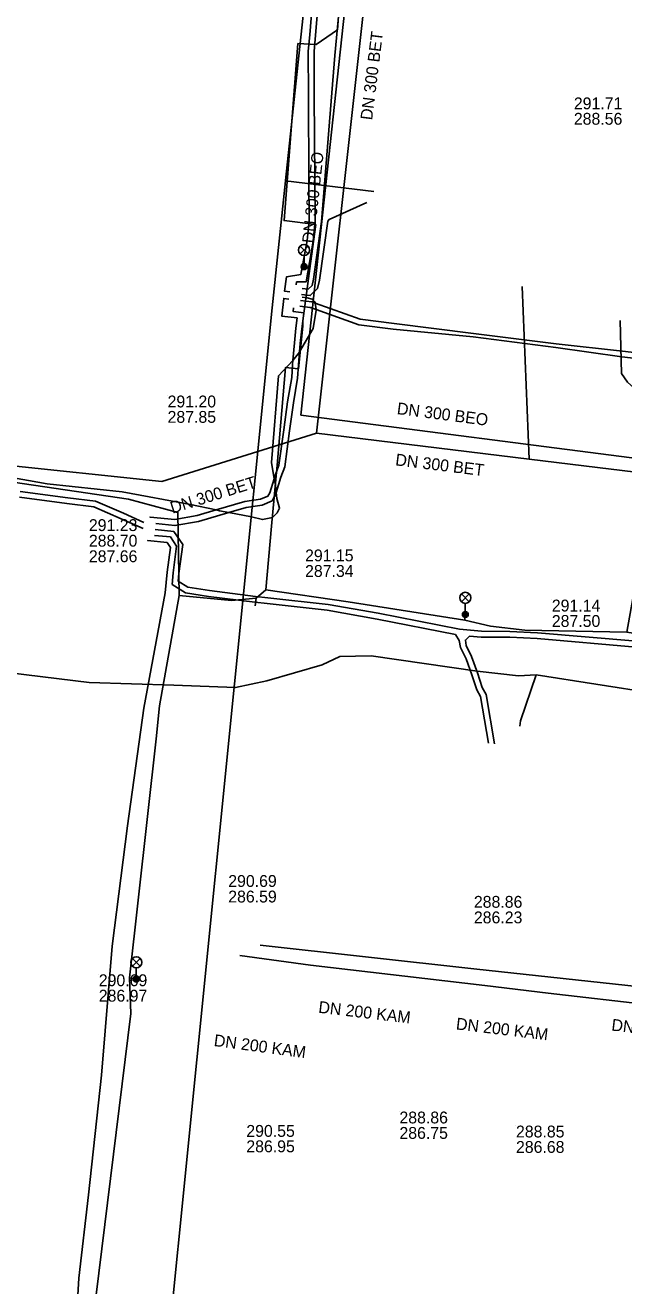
# Model space of a CAD drawing. Extents: x -595540 to -593988, y -1160850 to -1159202.
# Drawn here: x -594420.8 to -594380.4, y -1160378.8 to -1160293.7 of the extents above; entities that cross this region are included whole.
import ezdxf

# ---------------------------------------------------------------- set-up
doc = ezdxf.new("R2010")
doc.units = 0
for name, color, linetype in [('BVK-DESTOVA_popisy', 7, 'Continuous'), ('BVK-DESTOVA_trasa sítě', 7, 'Continuous'), ('BVK-SPLASKOVA_popisy', 7, 'Continuous'), ('BVK-SPLASKOVA_trasa sítě', 7, 'Continuous'), ('BVK-VODOVOD_trasa sítě', 7, 'Continuous'), ('CETIN_kabel podzemní', 7, 'Continuous'), ('DESTOVA-NEPROVOZOVANA_popisy', 7, 'Continuous'), ('DESTOVA_trasa neprovozované sítě', 7, 'Continuous'), ('EON-NN_kabel', 7, 'Continuous'), ('EON-VN_kabel', 7, 'Continuous'), ('SPLASKOVA_neprovozovaná  trasa sítě', 7, 'Continuous'), ('SPLASKOVA_popisy neprovozované sítě', 7, 'Continuous'), ('TSB_kabel VO', 7, 'Continuous'), ('TSB_lampy VO', 7, 'Continuous')]:
    doc.layers.add(name, color=color, linetype=linetype)

msp = doc.modelspace()

# ---------------------------------------------------------------- linework, layer by layer
at = {"layer": 'BVK-DESTOVA_popisy'}
msp.add_line((-594401.885, -1160330.032), (-594401.885, -1160330.032), dxfattribs=at)
at = {"layer": 'BVK-DESTOVA_trasa sítě'}
for points in [[(-594395.668, -1160272.407), (-594397.915, -1160292.572), (-594397.935, -1160292.748), (-594401.113, -1160321.262)], [(-594401.113, -1160321.262), (-594386.76, -1160323.019), (-594375.871, -1160324.352)]]:
    msp.add_lwpolyline(points, dxfattribs=at)
at = {"layer": 'BVK-SPLASKOVA_popisy'}
for p, q in [((-594383.751, -1160298.621), (-594383.751, -1160298.621)), ((-594411.161, -1160318.726), (-594411.161, -1160318.726)), ((-594385.238, -1160332.49), (-594385.238, -1160332.49))]:
    msp.add_line(p, q, dxfattribs=at)
at = {"layer": 'BVK-SPLASKOVA_trasa sítě'}
for p, q in [((-594396.883, -1160271.348), (-594402.178, -1160320.04)), ((-594402.178, -1160320.04), (-594376.811, -1160323.33))]:
    msp.add_line(p, q, dxfattribs=at)
at = {"layer": 'BVK-VODOVOD_trasa sítě'}
msp.add_line((-594403.199, -1160304.249), (-594397.24, -1160304.965), dxfattribs=at)
msp.add_lwpolyline([(-594414.304, -1160415.018), (-594414.26, -1160414.24), (-594404.1, -1160312.8), (-594403.199, -1160304.249), (-594403.197, -1160304.228), (-594393.45, -1160213.01), (-594381.18, -1160113.49), (-594372.864, -1160046.537), (-594372.845, -1160046.405)], dxfattribs=at)
at = {"layer": 'CETIN_kabel podzemní'}
for points in [[(-594484.42, -1160349.04), (-594484.05, -1160346.76), (-594483.66, -1160343.45), (-594482.72, -1160335.55), (-594481.74, -1160328.1), (-594481.2, -1160327.76), (-594478.86, -1160327.53), (-594466.54, -1160325.52), (-594458, -1160326.73), (-594452.76, -1160330.16), (-594444.1, -1160335.49), (-594430.62, -1160336.35), (-594416.44, -1160338.08), (-594410.73, -1160338.25), (-594406.57, -1160338.42), (-594404.47, -1160337.96), (-594400.72, -1160336.89), (-594399.54, -1160336.32), (-594397.42, -1160336.27), (-594390.27, -1160337.31), (-594387.49, -1160337.63), (-594386.29, -1160337.57)], [(-594386.29, -1160337.57), (-594387.36, -1160340.67), (-594387.4, -1160341.02)], [(-594386.29, -1160337.57), (-594378.24, -1160338.82), (-594374.04, -1160339.1), (-594368.53, -1160339.75), (-594365.35, -1160340.12), (-594364.77, -1160340.19)]]:
    msp.add_lwpolyline(points, dxfattribs=at)
at = {"layer": 'DESTOVA-NEPROVOZOVANA_popisy'}
for p, q in [((-594416.47, -1160329.965), (-594416.47, -1160329.965)), ((-594407.068, -1160352.915), (-594407.068, -1160352.915)), ((-594390.496, -1160354.321), (-594390.496, -1160354.321))]:
    msp.add_line(p, q, dxfattribs=at)
at = {"layer": 'DESTOVA_trasa neprovozované sítě'}
for p, q in [((-594387.235, -1160311.378), (-594386.76, -1160323.019)), ((-594454.646, -1160320.033), (-594411.539, -1160324.521)), ((-594411.539, -1160324.521), (-594401.113, -1160321.262)), ((-594404.921, -1160355.792), (-594390.492, -1160357.393)), ((-594390.492, -1160357.393), (-594368.695, -1160359.751))]:
    msp.add_line(p, q, dxfattribs=at)
at = {"layer": 'EON-NN_kabel'}
for points in [[(-594394.305, -1160238.002), (-594394.305, -1160238.183), (-594394.168, -1160238.409), (-594393.838, -1160238.499), (-594393.681, -1160238.791), (-594394.009, -1160241.492), (-594394.9, -1160250.248), (-594395.827, -1160258.292), (-594397.026, -1160267.983), (-594397.728, -1160272.871), (-594398.016, -1160276.318), (-594398.324, -1160281.565), (-594399.215, -1160288.846), (-594399.869, -1160295.788), (-594400.773, -1160306.992), (-594401.305, -1160310.873), (-594401.401, -1160311.295), (-594401.68, -1160311.561), (-594402.087, -1160311.513)], [(-594401.216, -1160290.139), (-594401.568, -1160294.397), (-594401.67, -1160295.504), (-594401.661, -1160298.46), (-594401.634, -1160304.184), (-594401.597, -1160306.916), (-594401.744, -1160308.27), (-594402.166, -1160310.552), (-594403.148, -1160310.72), (-594403.263, -1160311.69), (-594402.919, -1160311.73)], [(-594400.818, -1160290.173), (-594401.17, -1160294.431), (-594401.27, -1160295.522), (-594401.261, -1160298.458), (-594401.234, -1160304.18), (-594401.197, -1160306.934), (-594401.346, -1160308.312), (-594401.803, -1160311.046), (-594402.46, -1160311.068), (-594402.482, -1160311.261)], [(-594402.135, -1160311.91), (-594401.54, -1160311.981), (-594401.038, -1160311.501), (-594400.911, -1160310.945), (-594400.352, -1160306.966), (-594400.268, -1160306.851), (-594397.722, -1160305.704)], [(-594402.23, -1160312.705), (-594401.531, -1160312.788), (-594401.144, -1160312.928), (-594398.262, -1160313.966), (-594395.93, -1160314.254), (-594390.544, -1160314.774), (-594384.971, -1160315.481), (-594380.518, -1160316.122), (-594376.399, -1160316.597), (-594372.566, -1160316.533), (-594371.747, -1160316.261), (-594371.18, -1160315.757), (-594370.718, -1160314.861), (-594370.774, -1160313.871), (-594370.857, -1160312.452), (-594370.97, -1160312.168), (-594377.717, -1160311.167)], [(-594402.182, -1160312.308), (-594401.438, -1160312.397), (-594401.193, -1160312.485), (-594398.168, -1160313.574), (-594395.88, -1160313.858), (-594390.514, -1160314.537), (-594384.945, -1160315.242), (-594380.474, -1160315.724), (-594376.379, -1160316.197), (-594372.634, -1160316.135), (-594371.951, -1160315.907), (-594371.502, -1160315.507), (-594371.124, -1160314.775), (-594371.174, -1160313.893), (-594371.254, -1160312.53), (-594377.776, -1160311.562)], [(-594402.09, -1160312.08), (-594401.74, -1160312.14), (-594401.4, -1160312.22), (-594401.2, -1160312.42), (-594401.193, -1160312.485), (-594401.144, -1160312.928), (-594401.14, -1160312.96), (-594401.34, -1160314.21), (-594402.257, -1160315.785), (-594402.26, -1160315.79), (-594402.707, -1160316.356), (-594402.71, -1160316.36), (-594403.67, -1160317.39), (-594404.15, -1160323.25), (-594403.965, -1160324.339), (-594403.89, -1160324.78), (-594403.841, -1160325.258), (-594403.8, -1160325.66), (-594403.6, -1160326.33), (-594403.77, -1160326.64), (-594404.08, -1160326.96), (-594404.76, -1160327.09), (-594405.5, -1160326.9), (-594407.024, -1160326.609), (-594407.65, -1160326.49), (-594407.877, -1160326.443), (-594409.62, -1160326.08), (-594414.23, -1160325.22), (-594419.28, -1160324.67), (-594422.18, -1160324.16)], [(-594412.341, -1160326.942), (-594412.339, -1160326.918), (-594410.679, -1160327.089), (-594409.167, -1160326.821), (-594407.877, -1160326.443), (-594405.938, -1160325.874), (-594404.884, -1160325.724), (-594404.393, -1160325.519), (-594404.273, -1160325.294), (-594403.965, -1160324.339), (-594403.892, -1160324.112), (-594403.648, -1160323.43), (-594403.32, -1160321.047), (-594403.07, -1160319.159), (-594402.785, -1160317.504), (-594402.731, -1160316.635), (-594402.707, -1160316.356), (-594402.606, -1160315.179), (-594402.507, -1160314.182), (-594402.424, -1160313.49), (-594403.462, -1160313.368), (-594403.321, -1160312.18), (-594402.977, -1160312.221)], [(-594402.668, -1160312.8), (-594402.698, -1160313.054), (-594401.979, -1160313.139), (-594402.109, -1160314.226), (-594402.208, -1160315.215), (-594402.257, -1160315.785), (-594402.333, -1160316.665), (-594402.387, -1160317.55), (-594402.674, -1160319.219), (-594402.924, -1160321.101), (-594403.258, -1160323.526), (-594403.514, -1160324.24), (-594403.841, -1160325.258), (-594403.903, -1160325.45), (-594404.107, -1160325.833), (-594404.778, -1160326.112), (-594405.854, -1160326.266), (-594407.024, -1160326.609), (-594409.075, -1160327.211), (-594410.668, -1160327.493), (-594411.959, -1160327.359)], [(-594412.755, -1160327.279), (-594414.142, -1160326.667), (-594416.019, -1160325.852), (-594417.9, -1160325.615), (-594421.105, -1160325.186)], [(-594412.798, -1160327.697), (-594414.302, -1160327.033), (-594416.125, -1160326.242), (-594417.952, -1160326.011), (-594421.157, -1160325.582)], [(-594379.503, -1160335.294), (-594386.196, -1160334.721), (-594388.065, -1160334.632), (-594389.978, -1160334.614), (-594391.462, -1160334.49), (-594396.956, -1160333.402), (-594400.331, -1160332.81), (-594404.392, -1160332.363), (-594405.233, -1160332.273), (-594408.343, -1160331.88), (-594409.803, -1160331.655), (-594410.442, -1160331.254), (-594410.393, -1160330.721), (-594410.142, -1160328.777), (-594410.742, -1160327.887), (-594412.001, -1160327.757)], [(-594412.502, -1160328.484), (-594412.504, -1160328.509), (-594411.197, -1160328.643), (-594410.974, -1160328.974), (-594411.188, -1160330.633), (-594411.316, -1160332.026), (-594412.763, -1160339.798), (-594413.864, -1160347.737), (-594414.896, -1160355.861), (-594415.623, -1160364.549), (-594416.501, -1160372.621), (-594417.155, -1160378.242), (-594417.531, -1160384.696), (-594418.347, -1160395.909), (-594419.494, -1160401.414), (-594419.575, -1160402.57), (-594419.868, -1160403.022), (-594419.994, -1160403.039), (-594420.297, -1160402.993)], [(-594389.511, -1160342.169), (-594390.055, -1160339.027), (-594390.299, -1160338.575), (-594390.625, -1160337.558), (-594391.014, -1160336.48), (-594391.397, -1160335.714), (-594391.489, -1160335.241), (-594391.745, -1160334.841), (-594397.03, -1160333.796), (-594400.387, -1160333.206), (-594404.436, -1160332.761), (-594405.279, -1160332.671), (-594408.399, -1160332.276), (-594409.945, -1160332.037), (-594410.862, -1160331.465), (-594410.79, -1160330.677), (-594410.558, -1160328.875), (-594410.969, -1160328.265), (-594412.042, -1160328.154)], [(-594379.545, -1160335.692), (-594386.222, -1160335.121), (-594388.077, -1160335.032), (-594389.996, -1160335.014), (-594390.783, -1160334.948), (-594391.072, -1160335.223), (-594391.015, -1160335.584), (-594390.646, -1160336.322), (-594390.247, -1160337.428), (-594389.929, -1160338.417), (-594389.671, -1160338.895), (-594389.098, -1160342.214)]]:
    msp.add_lwpolyline(points, dxfattribs=at)
at = {"layer": 'EON-VN_kabel'}
msp.add_lwpolyline([(-594380.637, -1160313.672), (-594380.543, -1160317.23), (-594380.125, -1160317.817), (-594379.707, -1160318.215), (-594377.689, -1160318.817), (-594372.185, -1160319.28), (-594369.39, -1160319.548), (-594364.66, -1160320.217), (-594362.154, -1160320.531), (-594357.005, -1160321.141), (-594354.472, -1160321.439), (-594346.476, -1160322.315), (-594344.196, -1160322.524), (-594336.591, -1160323.343), (-594326.615, -1160324.399)], dxfattribs=at)
at = {"layer": 'SPLASKOVA_neprovozovaná  trasa sítě'}
for p, q in [((-594406.281, -1160356.497), (-594401.518, -1160357.132)), ((-594401.518, -1160357.132), (-594389.747, -1160358.51)), ((-594389.747, -1160358.51), (-594385.476, -1160359.023)), ((-594385.476, -1160359.023), (-594368.316, -1160361.006))]:
    msp.add_line(p, q, dxfattribs=at)
at = {"layer": 'SPLASKOVA_popisy neprovozované sítě'}
for p, q in [((-594415.801, -1160357.759), (-594415.801, -1160357.759)), ((-594395.518, -1160367.016), (-594395.518, -1160367.016)), ((-594405.848, -1160367.92), (-594405.848, -1160367.92)), ((-594387.655, -1160367.962), (-594387.655, -1160367.962))]:
    msp.add_line(p, q, dxfattribs=at)
at = {"layer": 'TSB_kabel VO'}
for points in [[(-594399.037, -1160285.107), (-594399.704, -1160294.063), (-594401.144, -1160295.049), (-594402.367, -1160294.99), (-594403.306, -1160306.925), (-594401.169, -1160307.193), (-594401.554, -1160310.162), (-594401.951, -1160310.035), (-594401.554, -1160310.162), (-594402.043, -1160313.676), (-594402.035, -1160314.044), (-594402.33, -1160316.925), (-594403.199, -1160316.833), (-594403.763, -1160323.43), (-594404.148, -1160327.534), (-594404.54, -1160331.835), (-594405.18, -1160332.399), (-594405.258, -1160332.9)], [(-594364.854, -1160292.94), (-594365.189, -1160296.792), (-594365.822, -1160300.266), (-594366.415, -1160306.186), (-594366.233, -1160308.823), (-594366.643, -1160308.879), (-594366.233, -1160308.823), (-594366.783, -1160311.834), (-594367.266, -1160314.261), (-594367.93, -1160317.548), (-594371.575, -1160318.731), (-594374.987, -1160319.911), (-594377.854, -1160319.656), (-594378.681, -1160326.238), (-594380.182, -1160334.69), (-594387.061, -1160334.538), (-594389.368, -1160334.272), (-594391.113, -1160333.864), (-594398.984, -1160332.628), (-594404.54, -1160331.835), (-594405.18, -1160332.399), (-594405.258, -1160332.9)], [(-594505.239, -1160320.305), (-594504.78, -1160320.38), (-594503.646, -1160321.344), (-594496.566, -1160321.991), (-594496.491, -1160323.072), (-594495.676, -1160323.1), (-594489.541, -1160324.25), (-594486.738, -1160324.515), (-594485.761, -1160321.864), (-594482.876, -1160319.267), (-594477.618, -1160318.31), (-594476.538, -1160319.246), (-594475.733, -1160318.696), (-594448.99, -1160321.769), (-594423.733, -1160324.263), (-594413.793, -1160325.724), (-594410.466, -1160326.608), (-594410.38, -1160332.22), (-594406.852, -1160332.549), (-594405.18, -1160332.399), (-594405.258, -1160332.9)], [(-594405.258, -1160332.9), (-594405.18, -1160332.399), (-594406.852, -1160332.549), (-594410.38, -1160332.22), (-594411.697, -1160339.647), (-594411.924, -1160341.872), (-594413.732, -1160357.988), (-594413.273, -1160358.076), (-594413.732, -1160357.988), (-594413.63, -1160360.4), (-594416.373, -1160382.649), (-594416.561, -1160384.891), (-594416.845, -1160386.589), (-594416.45, -1160386.594), (-594416.845, -1160386.589), (-594417.162, -1160395.776), (-594417.746, -1160401.774), (-594418.188, -1160404.708), (-594418.599, -1160404.664)], [(-594327.555, -1160341.113), (-594343.576, -1160339.066), (-594346.07, -1160338.981), (-594348.326, -1160338.745), (-594348.266, -1160338.367), (-594348.326, -1160338.745), (-594365.579, -1160336.664), (-594367.85, -1160336.602), (-594369.949, -1160336.313), (-594369.887, -1160335.933), (-594369.949, -1160336.313), (-594380.182, -1160334.69), (-594387.061, -1160334.538), (-594389.368, -1160334.272), (-594391.113, -1160333.864), (-594391.073, -1160333.493), (-594391.113, -1160333.864), (-594398.984, -1160332.628), (-594404.54, -1160331.835), (-594405.18, -1160332.399), (-594405.258, -1160332.9)]]:
    msp.add_lwpolyline(points, dxfattribs=at)
at = {"layer": 'TSB_lampy VO'}
for p, q in [((-594402.216, -1160309.175), (-594401.686, -1160308.645)), ((-594402.216, -1160308.645), (-594401.686, -1160309.175)), ((-594402.216, -1160309.175), (-594401.686, -1160308.645)), ((-594402.216, -1160308.645), (-594401.686, -1160309.175)), ((-594401.951, -1160309.285), (-594401.951, -1160310.035)), ((-594401.951, -1160309.285), (-594401.951, -1160310.035)), ((-594391.338, -1160332.633), (-594390.808, -1160332.103)), ((-594391.338, -1160332.103), (-594390.808, -1160332.633)), ((-594391.338, -1160332.633), (-594390.808, -1160332.103)), ((-594391.338, -1160332.103), (-594390.808, -1160332.633)), ((-594391.073, -1160332.743), (-594391.073, -1160333.493)), ((-594391.073, -1160332.743), (-594391.073, -1160333.493)), ((-594413.538, -1160357.216), (-594413.008, -1160356.686)), ((-594413.538, -1160356.686), (-594413.008, -1160357.216)), ((-594413.538, -1160357.216), (-594413.008, -1160356.686)), ((-594413.538, -1160356.686), (-594413.008, -1160357.216)), ((-594413.273, -1160357.326), (-594413.273, -1160358.076)), ((-594413.273, -1160357.326), (-594413.273, -1160358.076))]:
    msp.add_line(p, q, dxfattribs=at)
for centre, radius in [((-594401.951, -1160308.91), 0.375), ((-594401.951, -1160308.91), 0.375), ((-594401.951, -1160310.035), 0.2), ((-594401.951, -1160310.035), 0.2), ((-594401.951, -1160310.035), 0.145), ((-594401.951, -1160310.035), 0.145), ((-594401.951, -1160310.035), 0.0876), ((-594401.951, -1160310.035), 0.0876), ((-594391.073, -1160332.368), 0.375), ((-594391.073, -1160332.368), 0.375), ((-594391.073, -1160333.493), 0.2), ((-594391.073, -1160333.493), 0.2), ((-594391.073, -1160333.493), 0.145), ((-594391.073, -1160333.493), 0.145), ((-594391.073, -1160333.493), 0.0876), ((-594391.073, -1160333.493), 0.0876), ((-594413.273, -1160356.951), 0.375), ((-594413.273, -1160356.951), 0.375), ((-594413.273, -1160358.076), 0.2), ((-594413.273, -1160358.076), 0.2), ((-594413.273, -1160358.076), 0.145), ((-594413.273, -1160358.076), 0.145), ((-594413.273, -1160358.076), 0.0876), ((-594413.273, -1160358.076), 0.0876)]:
    msp.add_circle(centre, radius, dxfattribs=at)

# ---------------------------------------------------------------- texts
at = {"layer": 'BVK-DESTOVA_popisy'}
for rotation, p in [(82.90699, (-594397.363, -1160300.18)), (352.9993, (-594395.825, -1160323.428))]:
    msp.add_text('DN 300 BET', height=0.8, rotation=rotation, dxfattribs=at).set_placement(p)
for s, p in [('291.15', (-594401.885, -1160329.907)), ('287.34', (-594401.885, -1160330.957))]:
    msp.add_text(s, height=0.8, dxfattribs=at).set_placement(p)
at = {"layer": 'BVK-SPLASKOVA_popisy'}
for s, p in [('291.71', (-594383.751, -1160299.421)), ('288.56', (-594383.751, -1160300.461)), ('291.20', (-594411.161, -1160319.526)), ('287.85', (-594411.161, -1160320.566)), ('291.14', (-594385.238, -1160333.29)), ('287.50', (-594385.238, -1160334.33))]:
    msp.add_text(s, height=0.8, dxfattribs=at).set_placement(p)
for rotation, p in [(83.76643, (-594401.298, -1160308.484)), (352.59823, (-594395.721, -1160319.97))]:
    msp.add_text('DN 300 BEO', height=0.8, rotation=rotation, dxfattribs=at).set_placement(p)
at = {"layer": 'DESTOVA-NEPROVOZOVANA_popisy'}
msp.add_text('DN 300 BET', height=0.8, rotation=17.36062, dxfattribs=at).set_placement((-594410.836, -1160326.701))
for s, p in [('291.23', (-594416.47, -1160327.865)), ('288.70', (-594416.47, -1160328.915)), ('287.66', (-594416.47, -1160329.965)), ('290.69', (-594407.068, -1160351.865)), ('286.59', (-594407.068, -1160352.915)), ('288.86', (-594390.496, -1160353.271)), ('286.23', (-594390.496, -1160354.321))]:
    msp.add_text(s, height=0.8, dxfattribs=at).set_placement(p)
at = {"layer": 'SPLASKOVA_popisy neprovozované sítě'}
for s, p in [('290.69', (-594415.801, -1160358.559)), ('286.97', (-594415.801, -1160359.599)), ('288.86', (-594395.518, -1160367.816)), ('290.55', (-594405.848, -1160368.72)), ('288.85', (-594387.655, -1160368.762)), ('286.75', (-594395.518, -1160368.856)), ('286.95', (-594405.848, -1160369.76)), ('286.68', (-594387.655, -1160369.802))]:
    msp.add_text(s, height=0.8, dxfattribs=at).set_placement(p)
for rotation, p in [(353.32293, (-594401.015, -1160360.348)), (353.15088, (-594391.733, -1160361.469)), (353.40817, (-594381.244, -1160361.549)), (352.40614, (-594408.071, -1160362.589))]:
    msp.add_text('DN 200 KAM', height=0.8, rotation=rotation, dxfattribs=at).set_placement(p)

doc.saveas('drawing.dxf')
